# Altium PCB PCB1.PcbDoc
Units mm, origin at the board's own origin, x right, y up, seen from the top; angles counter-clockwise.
Board outline 48.89 x 49.4 mm, 2 copper layers (Top Layer, Bottom Layer); 29 components, 25 nets, 116 pads, 0 vias.
Unrouted connection lines stored in the file: 1.
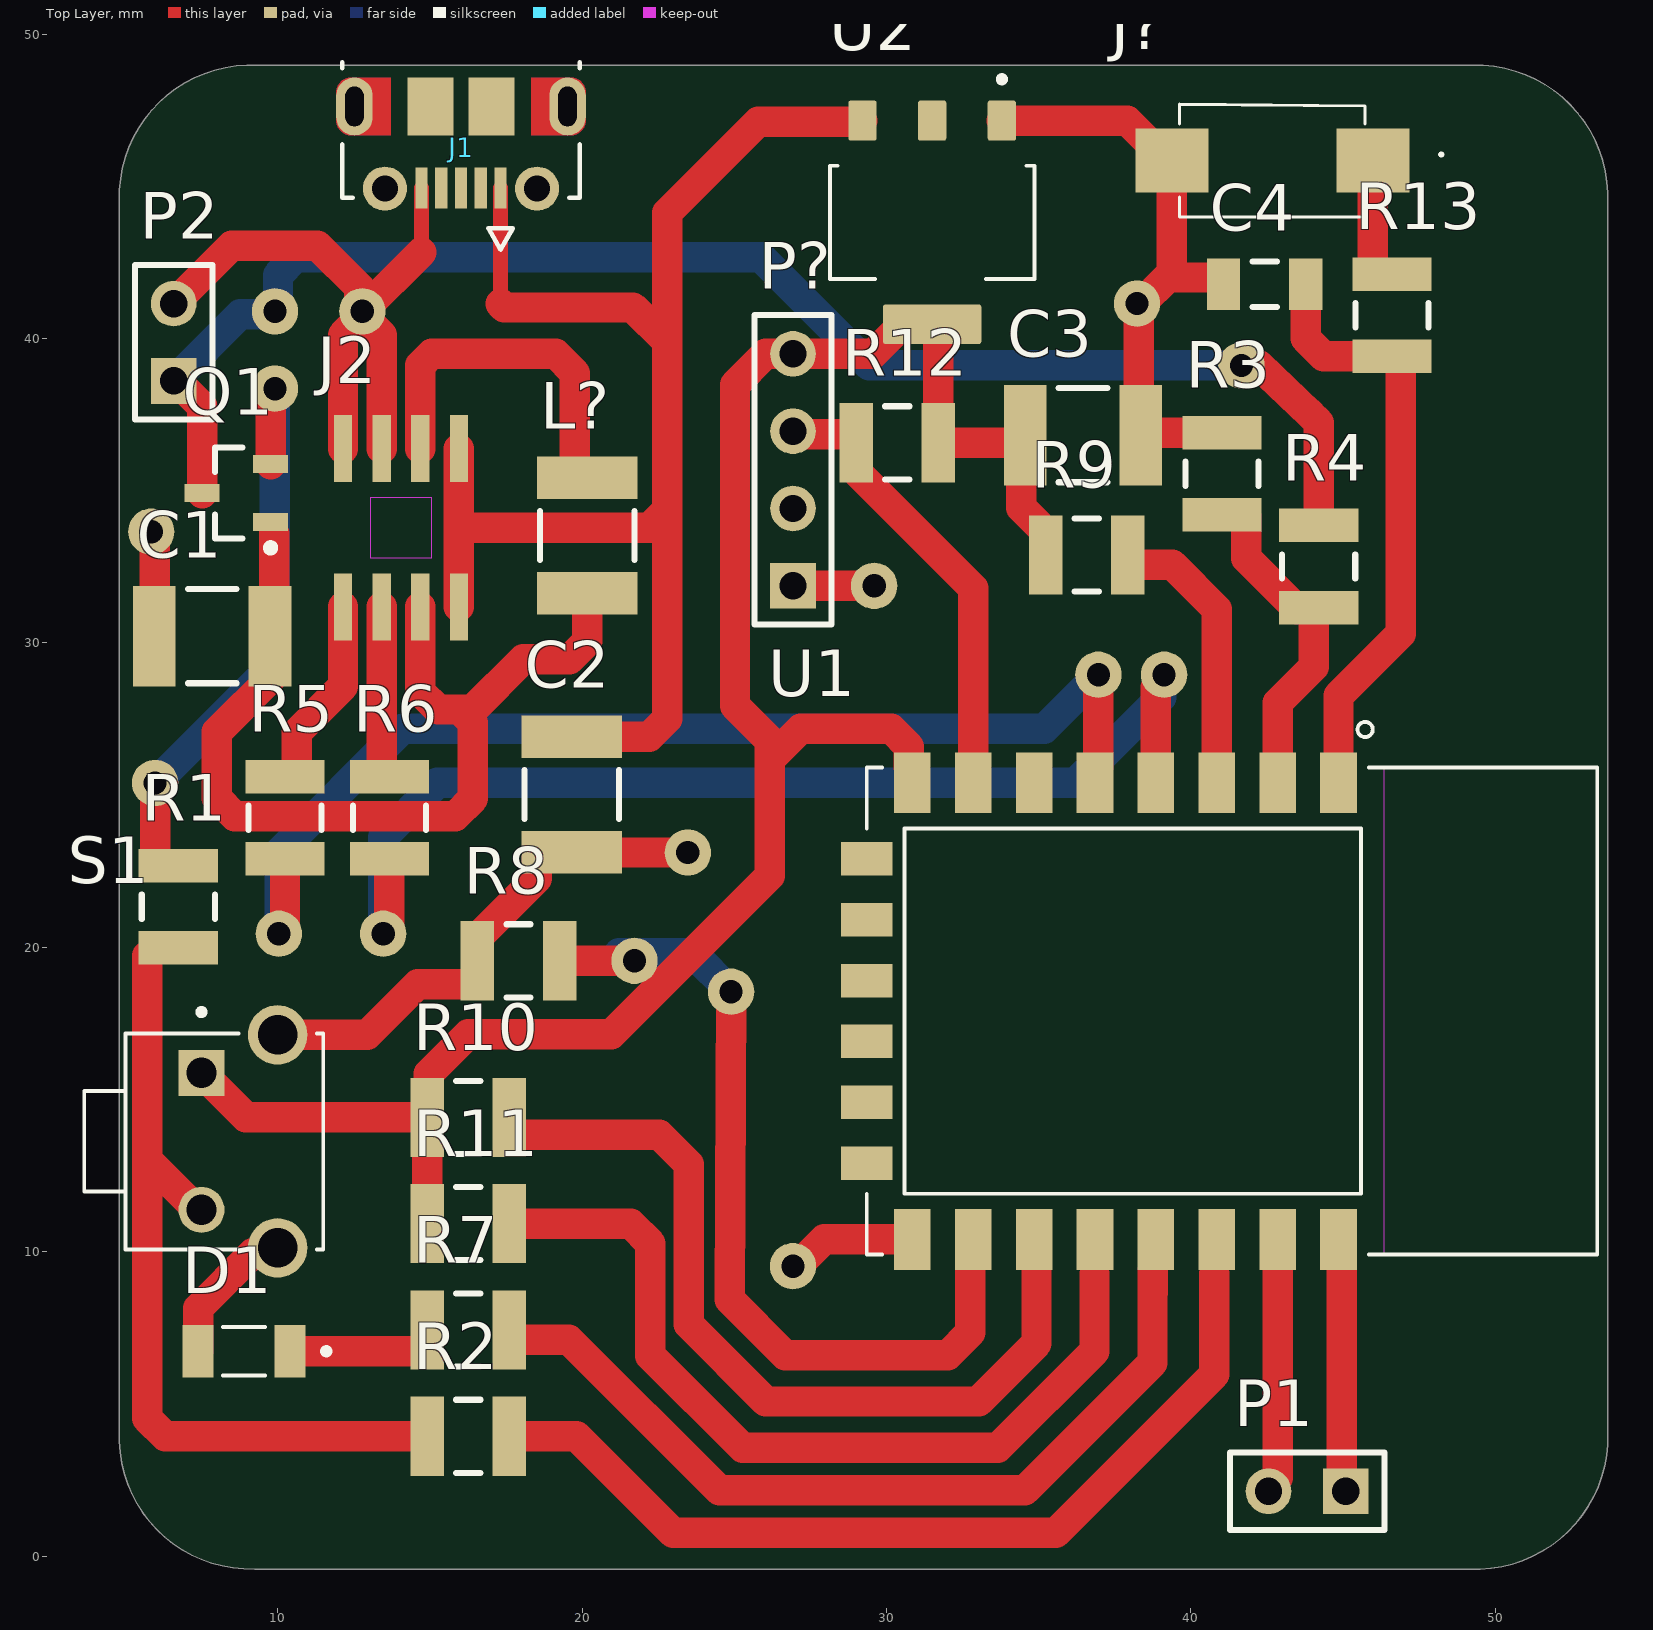
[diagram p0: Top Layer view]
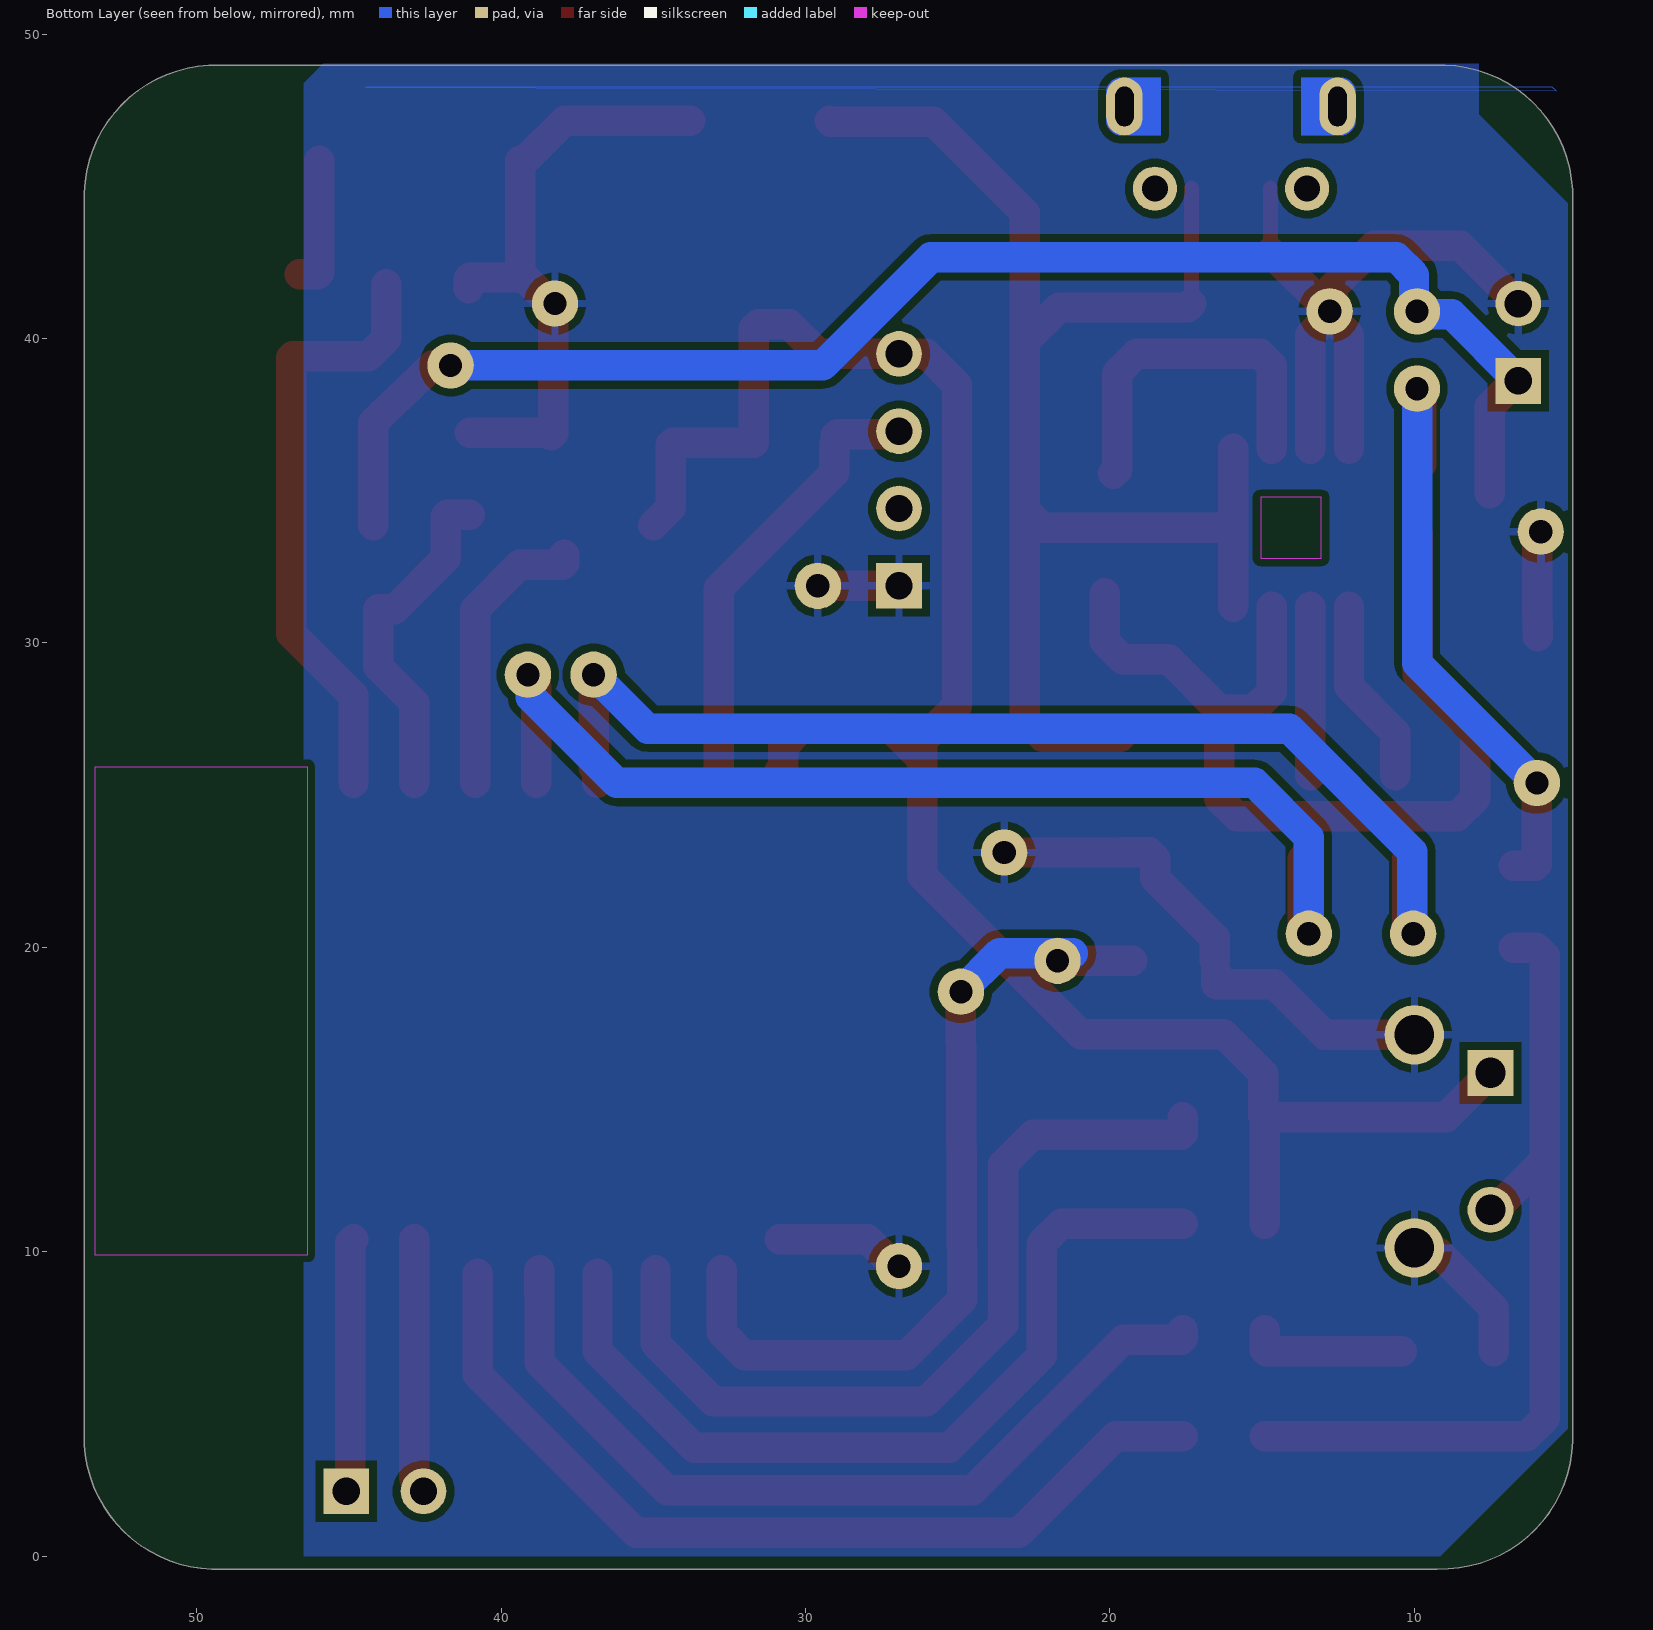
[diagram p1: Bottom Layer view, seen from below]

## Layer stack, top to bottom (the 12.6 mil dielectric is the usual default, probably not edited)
Top Solder: solder mask 0.0102, Solder Resist, Dk 3.5
Top Layer: signal copper 0.0356
Dielectric 1: dielectric 0.32, FR-4, Dk 4.8
Bottom Layer: signal copper 0.0356
Bottom Solder: solder mask 0.0102, Solder Resist, Dk 3.5

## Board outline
4.794,3.768 4.794,44.535 cw(c9.112,44.662) 8.985,48.98 49.244,48.98 cw(c49.371,44.662) 53.689,44.789 53.689,4.022 cw(c49.371,3.895) 49.498,-0.423 9.239,-0.423 cw(c9.112,3.895)

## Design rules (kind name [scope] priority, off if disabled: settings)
Clearance [All] p1: gap=0.254 ignorepadtopadclearanceinfootprint=FALSE except(0: Arc-Hole Track-Hole SMDPad-Hole THPad-Hole Via-Hole Fill-Hole Poly-Hole Region-Hole Text-Hole)
PolygonConnect [All] p1: connectstyle=Relief reliefconductorwidth=0.254 reliefentries=4 polygonreliefangle="90 Angle" airgapwidth=0.254
RoomDefinition Sheet1 [InComponentClass('Sheet1')] p1: confinementstyle=ConfineIn formatcopy=TRUE lockcomponents=FALSE outline 160.369,-49.826 352.901,-49.826 352.901,-19.092 160.369,-19.092
RoutingVias [All] p1: holewidth=0.711 width=1.27 viastyle="Through Hole" minholewidth=0.711 minwidth=1.27 maxholewidth=0.711 maxwidth=1.27
SolderMaskExpansion [All] p1: expansion=0.102 istentingtop=FALSE
Width [All] p1: maxlimit=1 minlimit=1 preferedwidth=1 minimp=50.000000 maximp=50.000000 favimp=50.000000
30 further rules are at their usual default settings.

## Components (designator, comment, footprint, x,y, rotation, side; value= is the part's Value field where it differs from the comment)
C1 "" 1812 7.844,30.226 r180 top value=10uF
C2 "" 1812 19.66,25.019 r270 top value=10uF
C3 "" 1812 36.449,36.83 r0 top value=10uF
C4 "" C1206 42.418,41.783 r0 top value=100pF
D1 "LED" LEDC3216X120N 8.89,6.731 r180 top
J1 "1050170001" MOLEX_1050170001 16.018,49.075 r180 top
J2 "L9110" SO-08 14.046,33.782 r0 top
J? "SWITCH" PTS636SM25FSMTRLFS 42.672,45.847 r180 top
L? "Inductor" INDC4532 20.168,33.528 r90 top value=47uH
P1 "Battery" HDR1X2 45.085,2.132 r180 top
P2 "Battery" HDR1X2 6.579,38.608 r90 top
P? "Header 4" HDR1X4 26.924,31.877 r90 top
Q1 "PNP" SOT-23B_N 8.636,34.925 r180 top
R1 "" 14-1210 6.731,21.336 r90 top value=1K
R2 "" 14-1210 16.256,3.937 r0 top value=1K
R3 "" 14-1210 41.021,35.56 r90 top value=1K
R4 "" 14-1210 44.196,32.512 r90 top value=1K
R5 "" 14-1210 10.236,24.257 r270 top value=1K
R6 "" 14-1210 13.665,24.257 r270 top value=1K
R7 "" 14-1210 16.256,7.43 r180 top value=1K
R8 "" 14-1210 17.907,19.558 r180 top value=1K
R9 "" 14-1210 36.576,32.893 r180 top value=1K
R10 "" 14-1210 16.256,14.414 r180 top value=1K
R11 "" 14-1210 16.256,10.922 r180 top value=1K
R12 "" 14-1210 30.353,36.576 r180 top value=1K
R13 "" 14-1210 46.609,40.767 r90 top value=1K
S1 "TL1105VF160Q" SW_TL1105VF160Q 7.493,13.625 r270 top
U1 "ESP8266-12E/ESP-12E" XCVR_ESP8266-12E/ESP-12E 37.846,17.907 r270 top
U2 "AMS1117" SOT229P700X180-4N 31.496,43.815 r270 top

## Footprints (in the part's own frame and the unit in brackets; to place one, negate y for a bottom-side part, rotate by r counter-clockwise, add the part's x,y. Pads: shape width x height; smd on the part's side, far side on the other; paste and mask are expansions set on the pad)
14-1210 [mm] "Chip Resistor, Body 3.2x2.5mm, IPC High Density"
  rect 1.1x2.6 smd: 1(-1.35,0) 2(1.35,0)
  silkscreen extent -0.4,-1.2 0.4,1.2, body extent -1.68,-1.32 1.68,1.32, height 0.9
1812 [mm] "Chip Capacitor, Body 4.5x3.2mm, IPC High Density"
  rect 1.4x3.3 smd: 1(-1.9,0) 2(1.9,0)
  silkscreen extent -0.8,-1.55 0.8,1.55, body extent -2.4,-1.7 2.4,1.7, height 1.4
C1206 [mm] "Chip Capacitor, Body 3.2x1.6mm, IPC High Density"
  rect 1.1x1.7 smd: 1(-1.35,0) 2(1.35,0)
  silkscreen extent -0.4,-0.75 0.4,0.75, body extent -1.7,-0.9 1.7,0.9, height 1.3
HDR1X2 [mm] "Connector; Header; 2 Position"
  rect 1.5x1.5 hole 0.9: 1(0,0)
  round 1.5 hole 0.9: 2(2.54,0)
  silkscreen extent -1.27,-1.27 3.81,1.27
HDR1X4 [mm] "Connector; Header; 4 Position"
  rect 1.5x1.5 hole 0.9: 1(0,0)
  round 1.5 hole 0.9: 2(2.54,0) 3(5.08,0) 4(7.62,0)
  silkscreen extent -1.27,-1.27 8.89,1.27
INDC4532 [mm] "Chip Inductor, Body 4.5x3.2mm, IPC High Density"
  rect 1.4x3.3 smd: 1(-1.9,0) 2(1.9,0)
  silkscreen extent -0.8,-1.55 0.8,1.55, body extent -2.4,-1.7 2.4,1.7, height 0.55
LEDC3216X120N [mm]
  rect 1.01x1.73 smd: NEG(1.51,0) POS(-1.51,0)
  silkscreen extent -2.8,-0.8 0.68,0.8, body extent -1.6,-0.8 1.6,0.8, height 1.2
MOLEX_1050170001 [mm]
  rect 0.4x1.35 smd mask+0.064: 1(-1.3,4.125) 2(-0.65,4.125) 3(0,4.125) 4(0.65,4.125) 5(1.3,4.125)
  round 1.45 hole 0.85 mask+0.064: SH1(-2.5,4.15) SH2(2.5,4.15)
  oval 1.2x1.9 hole 0.6 slot 1.3 at 90 deg mask+0: SH3(-3.5,1.45) SH6(3.5,1.45)
  rect 1.5x1.9 smd mask+0.064: SH4(-1,1.45) SH5(1,1.45)
  Top Layer region: -2.3,0.5 -3.6,0.5 -3.626,0.501 -3.652,0.503 -3.678,0.506 -3.704,0.511 -3.729,0.517 -3.755,0.524 -3.779,0.533 -3.803,0.543 -3.827,0.554 -3.85,0.567 -3.872,0.581 -3.894,0.595 -3.915,0.611 -3.935,0.628 -3.954,0.646 -3.972,0.665 -3.989,0.685 -4.005,0.706 -4.019,0.728 -4.033,0.75 -4.046,0.773 -4.057,0.797 -4.067,0.821 -4.076,0.845 -4.083,0.871 -4.089,0.896 -4.094,0.922 -4.097,0.948 -4.099,0.974 -4.1,1 -4.1,1.9 -4.099,1.926 -4.097,1.952 -4.094,1.978 -4.089,2.004 -4.083,2.029 -4.076,2.055 -4.067,2.079 -4.057,2.103 -4.046,2.127 -4.033,2.15 -4.019,2.172 -4.005,2.194 -3.989,2.215 -3.972,2.235 -3.954,2.254 -3.935,2.272 -3.915,2.289 -3.894,2.305 -3.872,2.319 -3.85,2.333 -3.827,2.346 -3.803,2.357 -3.779,2.367 -3.755,2.376 -3.729,2.383 -3.704,2.389 -3.678,2.394 -3.652,2.397 -3.626,2.399 -3.6,2.4 -2.3,2.4
  Top Layer region: 3.626,2.399 3.652,2.397 3.678,2.394 3.704,2.389 3.729,2.383 3.755,2.376 3.779,2.367 3.803,2.357 3.827,2.346 3.85,2.333 3.872,2.319 3.894,2.305 3.915,2.289 3.935,2.272 3.954,2.254 3.972,2.235 3.989,2.215 4.005,2.194 4.019,2.172 4.033,2.15 4.046,2.127 4.057,2.103 4.067,2.079 4.076,2.055 4.083,2.029 4.089,2.004 4.094,1.978 4.097,1.952 4.099,1.926 4.1,1.9 4.1,1 4.099,0.974 4.097,0.948 4.094,0.922 4.089,0.896 4.083,0.871 4.076,0.845 4.067,0.821 4.057,0.797 4.046,0.773 4.033,0.75 4.019,0.728 4.005,0.706 3.989,0.685 3.972,0.665 3.954,0.646 3.935,0.628 3.915,0.611 3.894,0.595 3.872,0.581 3.85,0.567 3.827,0.554 3.803,0.543 3.779,0.533 3.755,0.524 3.729,0.517 3.704,0.511 3.678,0.506 3.652,0.503 3.626,0.501 3.6,0.5 2.3,0.5 2.3,2.4 3.6,2.4
  Bottom Layer region: 3.626,2.399 3.652,2.397 3.678,2.394 3.704,2.389 3.729,2.383 3.755,2.376 3.779,2.367 3.803,2.357 3.827,2.346 3.85,2.333 3.872,2.319 3.894,2.305 3.915,2.289 3.935,2.272 3.954,2.254 3.972,2.235 3.989,2.215 4.005,2.194 4.019,2.172 4.033,2.15 4.046,2.127 4.057,2.103 4.067,2.079 4.076,2.055 4.083,2.029 4.089,2.004 4.094,1.978 4.097,1.952 4.099,1.926 4.1,1.9 4.1,1 4.099,0.974 4.097,0.948 4.094,0.922 4.089,0.896 4.083,0.871 4.076,0.845 4.067,0.821 4.057,0.797 4.046,0.773 4.033,0.75 4.019,0.728 4.005,0.706 3.989,0.685 3.972,0.665 3.954,0.646 3.935,0.628 3.915,0.611 3.894,0.595 3.872,0.581 3.85,0.567 3.827,0.554 3.803,0.543 3.779,0.533 3.755,0.524 3.729,0.517 3.704,0.511 3.678,0.506 3.652,0.503 3.626,0.501 3.6,0.5 2.3,0.5 2.3,2.4 3.6,2.4
  Bottom Layer region: -2.3,0.5 -3.6,0.5 -3.626,0.501 -3.652,0.503 -3.678,0.506 -3.704,0.511 -3.729,0.517 -3.755,0.524 -3.779,0.533 -3.803,0.543 -3.827,0.554 -3.85,0.567 -3.872,0.581 -3.894,0.595 -3.915,0.611 -3.935,0.628 -3.954,0.646 -3.972,0.665 -3.989,0.685 -4.005,0.706 -4.019,0.728 -4.033,0.75 -4.046,0.773 -4.057,0.797 -4.067,0.821 -4.076,0.845 -4.083,0.871 -4.089,0.896 -4.094,0.922 -4.097,0.948 -4.099,0.974 -4.1,1 -4.1,1.9 -4.099,1.926 -4.097,1.952 -4.094,1.978 -4.089,2.004 -4.083,2.029 -4.076,2.055 -4.067,2.079 -4.057,2.103 -4.046,2.127 -4.033,2.15 -4.019,2.172 -4.005,2.194 -3.989,2.215 -3.972,2.235 -3.954,2.254 -3.935,2.272 -3.915,2.289 -3.894,2.305 -3.872,2.319 -3.85,2.333 -3.827,2.346 -3.803,2.357 -3.779,2.367 -3.755,2.376 -3.729,2.383 -3.704,2.389 -3.678,2.394 -3.652,2.397 -3.626,2.399 -3.6,2.4 -2.3,2.4
  silkscreen extent -3.9,0 3.9,6.15
PTS636SM25FSMTRLFS [mm]
  rect 2.4x2.1 smd: 1(-3.3,0) 2(3.3,0)
  silkscreen extent -5.6,-1.85 3.05,1.85, body extent -4.29,-2.8 4.29,0, height 1.85
SO-08 [mm]
  rect 0.6x2.2 smd: 1(-1.905,-2.6) 2(-0.635,-2.6) 3(0.635,-2.6) 4(1.905,-2.6) 5(1.905,2.6) 6(0.635,2.6) 7(-0.635,2.6) 8(-1.905,2.6)
  Keep-Out Layer region: 1,-1 -1,-1 -1,1 1,1
SOT229P700X180-4N [mm]
  rrect15% 1.31x0.93 smd: 1(-3.345,2.29) 2(-3.345,0) 3(-3.345,-2.29)
  rrect15% 1.31x3.24 smd: 4(3.345,0)
  silkscreen extent -4.8,-3.36 1.86,3.36, body extent -3.25,-3.5 3.25,3.5, height 1.8
SOT-23B_N [mm] "SOT23, 3-Leads, Body 2.9x1.3mm, Pitch 0.95mm, Lead Span 2.4mm, IPC Medium Density"
  rect 1.15x0.6 smd: 1(-1.125,0.95) 2(-1.125,-0.95) 3(1.125,0)
  silkscreen extent -1.25,-1.5 0.7,1.92, body extent -0.7,-1.5 0.7,1.5, height 1.14
SW_TL1105VF160Q [mm]
  rect 1.508x1.508 / inner round 1.508 / far side rect 1.508x1.508 hole 1 mask+0.102: 1(-2.25,0)
  round 1.508 hole 1 mask+0.102: 2(2.25,0)
  round 1.95 hole 1.3 mask+0.102: S1(-3.5,2.5) S2(3.5,2.5)
  silkscreen extent -4.35,-3.85 3.55,4, body extent -7.7,-4.64 3.3,3.21, height 4.2
XCVR_ESP8266-12E/ESP-12E [mm]
  rect 2x1.2 smd: 1(-7.5,7) 2(-7.5,5) 3(-7.5,3) 4(-7.5,1) 5(-7.5,-1) 6(-7.5,-3) 7(-7.5,-5) 8(-7.5,-7) 15(7.5,-7) 16(7.5,-5) 17(7.5,-3) 18(7.5,-1) 19(7.5,1) 20(7.5,3) 21(7.5,5) 22(7.5,7)
  rect 1.1x1.7 smd: 9(-5,-8.5) 10(-3,-8.5) 11(-1,-8.5) 12(1,-8.5) 13(3,-8.5) 14(5,-8.5)
  Keep-Out Layer region: 8,8.51 -8.009,8.51 -8.009,15.5 8,15.5
  Keep-Out Layer region: 8,8.51 -8.009,8.51 -8.009,15.5 8,15.5
  silkscreen extent -9.5,-8.5 8,15.5, body extent -8,-12 8,12, height 3

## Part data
C1 C2 C3: library part "Cap Pol3", "Polarized Capacitor (Surface Mount)"
C4: library part "Cap Semi", "Capacitor (Semiconductor SIM Model)"
D1: library part LHN974_RED_LED_1206, "2.6 V Red LED SMD", Package=None
J1: "USB - micro B USB 2.0 Receptacle Connector 5 Position Surface Mount, Right Angle; Through Hole", Package=None
J2: "Motor control driver chip", Package=Package
J?: library part PTS636_SM25F_SMTR_LFS, "Tactile Switch SPST-NO Top Actuated Surface Mount", Package=None
P1 P2: library part "Header 2", "Header, 2-Pin"
P?: "Header, 4-Pin"
Q1: "PNP Bipolar Transistor"
R1 R2 R3 R4 R5 R6 R7 R8 R9 R10 R11 R12 R13: library part Res3, "Resistor"
S1: "Tactile Switch, TL1105 Series, SPST-NO, 3.85mm Side Actuated, 0.05A, 12VDC, PC", Package=None
U1: "This WiFi module has a 32-bit MCU micro and clock speeds supporting 80 MHz or 160 MHz. Supports the RTOS and integrated Wi-Fi MAC/BB/RF/PA/LNA, and has an on-board antenna.", Package=None
U2: "1A LOW DROPOUT VOLTAGE REGULATOR SOT-223", Package="SOT-223 Seeed Technology"

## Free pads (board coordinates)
  round 1.524 hole 0.762: 2(12.776,40.894) 3(23.47,23.114) 4(5.842,33.655) 5(5.969,25.4) 6(9.906,38.354) 7(24.892,18.542) 8(21.717,19.558) 9(38.227,41.148) 10(29.591,31.877) 11(26.924,9.525) 12(10.033,20.447) 13(13.462,20.447) 14(36.957,28.956) 15(39.116,28.956) 16(9.906,40.894) 17(41.656,39.116)

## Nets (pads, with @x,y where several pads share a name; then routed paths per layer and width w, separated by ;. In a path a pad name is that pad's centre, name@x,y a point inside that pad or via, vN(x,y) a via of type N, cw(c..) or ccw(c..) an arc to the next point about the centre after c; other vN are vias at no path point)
+3.3: C3.1 P?.4 R9.2 R10.2 R11.2 R12.1 S1.1 U1.8 U2.2 U2.4 | length 66.9
  Top Layer w1: S1.1 8.954,14.414 R10.2 ; R11.2 R10.2 ; U1.8 30.846,25.807 30.734,25.919 30.734,26.592 30.148,27.178 27.178,27.178 26.162,26.162 ; R9.2@35.005,33.862 34.419,34.448 34.419,36.506 34.349,36.576 R12.1 31.703,40.315 31.548,40.47 U2.4 30.531,40.47 29.558,39.497 P?.4 26.035,39.497 25.019,38.481 25.019,27.94 26.162,26.797 26.162,26.162 ; R10.2 14.956,14.464 14.956,15.845 16.256,17.145 20.955,17.145 26.162,22.352 26.162,26.162
+5: C2.1 J1.1 J2.4 J2.5 U2.3 | length 49.8
  Top Layer w0.5: 17.318,41.148 J1.1
  Top Layer w1: J2.4 15.951,33.782 ; J2.5 15.951,33.782 ; 17.318,41.148 17.445,41.021 21.666,41.021 22.792,39.895 ; C2.1 22.206,26.919 22.792,27.505 22.792,34.368 ; U2.3 29.206,47.152 29.171,47.117 25.781,47.117 22.792,44.128 22.792,39.895 ; 15.951,33.782 22.206,33.782 22.792,34.368 ; 22.792,34.368 22.792,39.895
ADC: R3.1 R4.1 U1.2 | length 11.3
  Top Layer w1: R3.1 41.771,34.21 41.821,34.16 41.821,32.787 43.496,31.112 44.031,31.112 44.031,29.219 42.846,28.034 U1.2
Battery: P2.1 pad.16 pad.17 Q1.3 R4.2 | length 49.7
  Top Layer w1: P2.1 6.829,38.358 6.925,38.358 7.511,37.772 Q1.3 ; pad.17 41.808,39.12 41.821,39.12 42.233,39.12 43.894,37.542 43.903,37.533 44.196,37.24 R4.2
  Bottom Layer w1: P2.1 8.764,40.794 9.806,40.794 10.006,40.994 10.006,42.086 10.592,42.672 25.876,42.672 29.432,39.116 pad.17
EN: R9.1 U1.3 | length 9.5
  Top Layer w1: R9.1 37.926,32.618 37.976,32.568 39.39,32.568 40.846,31.112 U1.3
GND: C1.2 C2.2 C3.2 C4.1 D1.NEG J1.5 J2.7 J2.8 J?.2 P2.2 P?.1 pad.2 pad.3 pad.4 pad.9 pad.10 pad.11 R3.2 R8.2 S1.S1 S1.S2 U1.15 U2.1 | length 75.3
  Top Layer w0.5: 14.718,42.836 J1.5
  Top Layer w1: pad.4 5.882,33.68 5.956,33.605 5.956,31.376 C1.2 ; P2.2 8.484,43.053 11.303,43.053 12.676,41.68 12.676,40.994 pad.2 ; D1.NEG 7.385,6.736 7.385,8.147 9.181,9.943 9.811,9.943 S1.S2 ; S1.S1 12.934,17.125 14.595,18.786 16.507,18.786 R8.2@16.507,19.177 ; J2.8 12.141,40.117 pad.2@12.776,40.752 ; J2.7 13.411,40.117 pad.2@12.776,40.752 ; 14.718,42.836 pad.2 ; R8.2 16.557,20.308 18.51,22.261 18.51,22.919 18.71,23.119 C2.2 19.662,23.116 23.467,23.116 pad.3 ; pad.11 27.066,9.525 27.948,10.407 U1.15 ; P?.1 pad.10 ; U2.1 37.909,47.16 39.222,45.847 J?.2 39.372,42.242 39.608,42.006 ; R3.2 38.429,36.91 C3.2 38.288,36.891 38.288,41.087 pad.9 38.369,41.148 39.227,42.006 39.608,42.006 ; C4.1@41.068,41.656 C4.1 41.068,41.956 41.018,42.006 39.608,42.006 ; pad.2@12.776,40.752 pad.2
GPIO0: R11.1 U1.18 | length 28.3
  Top Layer w1: R11.1 21.59,10.922 22.241,10.271 22.241,6.588 25.273,3.556 33.655,3.556 36.83,6.731 36.83,9.281
GPIO2: R10.1 U1.17 | length 27.8
  Top Layer w1: R10.1 17.606,13.893 17.656,13.843 22.528,13.843 23.495,12.876 23.495,7.62 26.035,5.08 33.02,5.08 34.925,6.985 34.925,9.398
GPIO4: R7.1 U1.19 | length 28.3
  Top Layer w1: R7.1 17.606,7.162 17.656,7.112 19.558,7.112 24.511,2.159 34.544,2.159 38.735,6.35 38.735,8.641 38.746,8.652 38.746,9.398
GPIO5: R2.2 U1.20 | length 29.9
  Top Layer w1: R2.2 19.812,3.937 22.987,0.762 35.56,0.762 40.767,5.969 40.767,9.271
GPIO13: P?.3 R12.2 U1.7 | length 15.1
  Top Layer w1: P?.3@26.924,36.861 28.953,36.861 29.003,36.811 R12.2 29.053,36.526 29.053,35.59 32.846,31.797 U1.7
GPIO14: pad.12 pad.14 R5.2 U1.5 | length 38.1
  Top Layer w1: pad.12 10.033,20.589 10.236,20.792 R5.2 ; U1.5 36.846,25.807 36.957,25.918 pad.14
  Bottom Layer w1: pad.12 10.061,20.475 10.061,23.142 14.097,27.178 35.179,27.178 pad.14
GPIO15: pad.7 pad.8 R8.1 U1.16 | length 27.8
  Top Layer w1: R8.1 pad.8 ; pad.7 24.844,8.43 26.67,6.604 32.004,6.604 32.746,7.346 32.746,9.398
  Bottom Layer w1: pad.8@21.209,19.812 23.622,19.812 pad.7
GPIO16: pad.13 pad.15 R6.2 U1.4 | length 37.6
  Top Layer w1: pad.13 13.462,20.589 13.665,20.792 R6.2 ; U1.4 38.846,28.544 39.116,28.814 pad.15
  Bottom Layer w1: pad.13 13.462,23.622 15.24,25.4 36.195,25.4 39.016,28.221 39.016,28.856 pad.15
L1: J2.1 R5.1 | length 6.2
  Top Layer w1: R5.1@10.617,25.657 10.617,27.051 12.141,28.575 J2.1
L2: J2.2 R6.1 | length 5.5
  Top Layer w1: R6.1@13.411,25.657 J2.2
NetC1_1: C1.1 J2.3 L?.1 Q1.1 | length 32.5
  Top Layer w1: 9.881,33.594 9.881,28.956 8.001,27.076 8.001,24.889 8.587,24.303 15.824,24.303 16.41,24.889 16.41,27.379 15.977,27.813 ; J2.3 14.681,28.399 15.267,27.813 15.977,27.813 ; L?.1 20.168,30.05 19.582,29.464 18.061,29.464 16.41,27.813 15.977,27.813
NetD1_POS: D1.POS R7.2 | length 5.2
  Top Layer w1: D1.POS 14.856,6.731 14.906,6.781 R7.2
NetJ2_6: J2.6 L?.2 | length 11.6
  Top Layer w1: J2.6 14.681,39.116 15.062,39.497 19.126,39.497 19.761,38.862 19.761,35.682 L?.2@19.888,35.555
NetJ?_1: J?.1 R13.2 | length 4.3
  Top Layer w1: J?.1 45.972,42.167 46.022,42.117 R13.2
NetR1_1: R1.1 R2.1 S1.2 | length 28.2
  Top Layer w1: R1.1 5.981,19.986 5.715,19.72 5.715,13.016 ; S1.2 7.356,11.375 5.715,13.016 ; R2.1 6.301,3.937 5.715,4.523 5.715,13.016
ON/OFF: pad.5 pad.6 Q1.2 R1.2 | length 20.6
  Top Layer w1: pad.5 5.969,22.736 6.019,22.686 R1.2 ; Q1.2 9.761,38.209 pad.6
  Bottom Layer w1: pad.5 9.906,29.337 pad.6
RESET: C4.2 R13.1 U1.1 | length 20
  Top Layer w1: C4.2 43.768,40.003 44.354,39.417 46.835,39.417 46.885,39.367 46.885,30.3 44.846,28.261 U1.1
RX: P1.2 U1.21 | length 8.4
  Top Layer w1: P1.2 42.545,2.267 42.846,2.568 U1.21
TX: P1.1 U1.22 | length 8.4
  Top Layer w1: U1.22 44.946,10.307 44.946,2.271 P1.1
pads on no net: J1.2 J1.3 J1.4 J1.SH1 J1.SH2 J1.SH3 J1.SH4 J1.SH5 J1.SH6 P?.2 U1.6 U1.9 U1.10 U1.11 U1.12 U1.13 U1.14

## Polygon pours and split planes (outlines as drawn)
GND on Bottom Layer "GND_L02_P004" (solid, pour order 4): 7.874,49.022 45.847,49.022 46.482,48.387 46.482,0 9.144,0 4.953,4.191 4.953,44.45 7.874,47.371
GND on Bottom Layer "GND_L02_P003" (solid, pour order 3): 5.334,48.133 5.461,48.26 44.45,48.26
